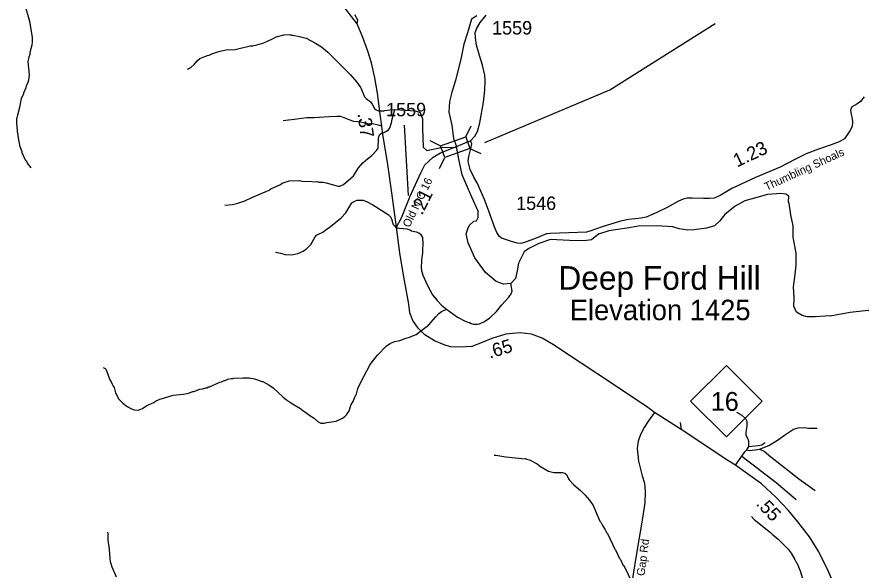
# Model space of a CAD drawing. Extents: x 1248224 to 1454986, y 825081 to 985870.
# Drawn here: x 1328841 to 1336688, y 907441 to 912588 of the extents above; entities that cross this region are included whole.
import ezdxf

# ---------------------------------------------------------------- set-up
doc = ezdxf.new("R2010")
doc.units = 0
for name, color, linetype in [('Exist Geographical Mountain Summit Elevation Number Label', 7, 'Continuous'), ('Exist Geographical Mountain Summit Label', 7, 'Continuous'), ('Exist Hydrographic Misc Water Feature', 7, 'Continuous'), ('Exist Hydrographic River Shore', 7, 'Continuous'), ('Exist Road Non-System Type 51', 7, 'Continuous'), ('Exist Road Primary NC Attributed', 7, 'Continuous'), ('Exist Road Primary NC Mileage Hundredths English Label', 7, 'Continuous'), ('Exist Road Primary NC Shield CELL', 7, 'Continuous'), ('Exist Road Primary NC Shield Number Label', 7, 'Continuous'), ('Exist Road Secondary Mileage Hundredths English Label', 7, 'Continuous'), ('Exist Road Secondary Structure Standard Bridge CELL', 7, 'Continuous'), ('Exist Road Secondary Structure Standard Bridge Number Label', 7, 'Continuous'), ('Exist Road Secondary Type 51 Attributed', 7, 'Continuous'), ('Exist Road Secondary Type 51 Label', 7, 'Continuous'), ('Exist Road Secondary Type 51 Number Label', 7, 'Continuous')]:
    doc.layers.add(name, color=color, linetype=linetype)

msp = doc.modelspace()

# ---------------------------------------------------------------- linework, layer by layer
at = {"layer": 'Exist Hydrographic Misc Water Feature'}
for points in [[(1328974.7, 911185), (1328939.9, 911226), (1328932.4, 911242.2), (1328924.6, 911250.4), (1328890.7, 911323.4), (1328890.9, 911331.4), (1328872.2, 911379.9), (1328858.1, 911444.3), (1328846.3, 911524.7), (1328840.5, 911604.8), (1328841.5, 911636.8), (1328848.5, 911676.5), (1328868.5, 911748), (1328884.8, 911827.5), (1328904.1, 911874.9), (1328904.4, 911882.9), (1328927.7, 911930.2), (1328930.2, 911948.1), (1328945.1, 911979.7), (1328951.8, 912001.4), (1328957.1, 912049.3), (1328946.4, 912169.6), (1328955.8, 912217.3), (1328964.5, 912241), (1328965, 912259), (1328982.9, 912328.5), (1328985.6, 912352.4), (1328985, 912400.4), (1328961, 912545), (1328913.5, 912706.4)], [(1330425.3, 912102.8), (1330457.6, 912115.9), (1330488.4, 912145), (1330515.4, 912178.2), (1330540, 912199.5), (1330572.4, 912214.6), (1330588.6, 912218.1), (1330612.9, 912229.4), (1330629, 912232.9), (1330653.3, 912244.2), (1330718, 912266.4), (1330782.4, 912280.4), (1330870.6, 912286), (1331007.5, 912317.9), (1331031.6, 912319.3), (1331071.9, 912328.1), (1331136.4, 912346.2), (1331217.5, 912383.9), (1331250.1, 912402.9), (1331322.6, 912420.8), (1331376.7, 912423.2), (1331390.6, 912418.8), (1331406.6, 912418.4), (1331414.5, 912414.1), (1331456.3, 912409), (1331529.8, 912390.8), (1331616.5, 912344.3), (1331673.6, 912308.7), (1331732.2, 912259), (1331940.4, 912049), (1332000.5, 911981.3), (1332037.1, 911928.2), (1332072.8, 911845.3), (1332088.3, 911828.8), (1332127.4, 911797.7), (1332142.9, 911777.2), (1332165.8, 911736.6), (1332179.4, 911724.2), (1332203.2, 911715.5), (1332251.2, 911714.2), (1332259.3, 911718), (1332307.5, 911724.5), (1332352.2, 911725.5)], [(1330773.8, 910835.1), (1330846.1, 910843), (1330894.3, 910853.7), (1330958.9, 910875.7), (1331023.9, 910907.9), (1331185.9, 910977.2), (1331202.2, 910988.7), (1331291.4, 911030.1), (1331307.8, 911041.6), (1331372.4, 911063.7), (1331466.5, 911065.1), (1331488.4, 911060.4), (1331582.4, 911057.7), (1331620.2, 911052.6), (1331634.4, 911056.2), (1331648.2, 911051.7), (1331686.3, 911050.7), (1331700.1, 911046.3), (1331716.1, 911045.8), (1331827.2, 911014.6), (1331843.2, 911014.1), (1331875.7, 911029.2), (1331945.3, 911087.2), (1331968, 911110.5), (1332016.1, 911183.1), (1332057.4, 911229.9), (1332098.5, 911266.7), (1332139.4, 911297.5), (1332184.7, 911344.2), (1332197.3, 911367.8), (1332201.9, 911455.7), (1332204.3, 911471.6), (1332212.9, 911493.3), (1332229.3, 911506.9), (1332245.4, 911510.3), (1332269.7, 911521.6), (1332294.2, 911538.9), (1332308.7, 911556.5), (1332324.1, 911604.1), (1332329, 911635.9), (1332352.2, 911725.5)], [(1332352.2, 911725.5), (1332456.7, 911720.5), (1332543, 911714.8), (1332589, 911697.5), (1332612, 911640), (1332612, 911553.7), (1332617.7, 911375.3), (1332652.2, 911346.5), (1332796, 911375.3), (1332929.9, 911373.4)], [(1331245.7, 910399.6), (1331291.4, 910390.2), (1331333.2, 910377.1), (1331397, 910373.2), (1331453.4, 910385.6), (1331502.1, 910408.2), (1331534.8, 910433.2), (1331573.9, 910470.1), (1331611.8, 910541), (1331626.3, 910556.5), (1331642.7, 910568.1), (1331683.2, 910586.9), (1331724.1, 910617.8), (1331756.6, 910636.7), (1331854.9, 910717.9), (1331898.3, 910764.7), (1331955, 910859), (1331971.3, 910870.5), (1332003.7, 910883.5), (1332059.7, 910883.9), (1332095.3, 910868.9), (1332150.5, 910839.3), (1332292.1, 910751.2), (1332315.4, 910724.6), (1332330.4, 910692.2), (1332330.2, 910684.2), (1332339.4, 910657.9), (1332360.9, 910635.3), (1332376.6, 910626.9), (1332396.4, 910622.3), (1332464.3, 910616.3), (1332492.1, 910607.5), (1332507.9, 910599.1), (1332551.7, 910589.8), (1332577.3, 910579), (1332593, 910566.6), (1332610.1, 910536.1), (1332609.5, 910512.2), (1332613.3, 910504.1), (1332610.1, 910392.2), (1332600.3, 910328.4), (1332598.1, 910248.6), (1332601.8, 910240.5), (1332601.4, 910224.5), (1332609, 910208.3), (1332614.2, 910184.1), (1332653.8, 910095), (1332705.3, 910003.5), (1332747.7, 909948.3), (1332788.5, 909905.1), (1332832.7, 909869)], [(1332832.7, 909869), (1332937.5, 909794.9), (1333008.4, 909756.8), (1333040.1, 909743.9), (1333048.1, 909743.7), (1333063.8, 909735.2), (1333083.7, 909730.7), (1333123.7, 909729.5), (1333139.8, 909733.1), (1333188.5, 909755.6), (1333237.4, 909788.2), (1333299.1, 909848.4), (1333348.9, 909910.9), (1333414.9, 909981), (1333423.4, 909996.8), (1333431.6, 910004.5), (1333444.5, 910036.1), (1333430.7, 910106.7)], [(1329642.8, 909326.2), (1329660.5, 909317.7), (1329666.4, 909309.6), (1329687.1, 909265), (1329701.8, 909216.6), (1329717, 909192.1), (1329735.9, 909151.6), (1329745.6, 909139.3), (1329756.2, 909091), (1329788.6, 909032.2), (1329825.5, 908993.1), (1329864.7, 908964), (1329906.1, 908942.8), (1329931.9, 908934.1), (1329967.8, 908931), (1329975.9, 908932.7), (1330008.3, 908945.9), (1330049, 908972.6), (1330113.8, 909000.7), (1330130.2, 909012.3), (1330170.7, 909031.1), (1330203.1, 909042.1), (1330291.8, 909067.6), (1330388.2, 909076.8), (1330436.5, 909087.3), (1330476.9, 909102.2), (1330484.9, 909102), (1330541.5, 909124.4), (1330565.6, 909127.6), (1330597.9, 909138.7), (1330605.9, 909138.5), (1330622.1, 909146), (1330630.1, 909145.8), (1330727.5, 909190.9), (1330743.6, 909194.5), (1330767.9, 909205.8), (1330775.9, 909205.6), (1330800.2, 909216.8), (1330832.4, 909223.9), (1330848.4, 909223.4), (1330856.6, 909227.2), (1330944.7, 909230.7), (1331000.7, 909229), (1331048.5, 909221.7), (1331119.8, 909195.6), (1331127.8, 909195.4), (1331183, 909165.8), (1331222.2, 909136.7), (1331315.8, 909049.9), (1331347.1, 909025.1), (1331394.3, 908995.7), (1331402, 908987.5), (1331476.9, 908945.3), (1331484.7, 908937.1), (1331539.6, 908899.5), (1331563.1, 908878.9), (1331602.4, 908853.8), (1331641.4, 908820.6), (1331665.1, 908808), (1331697.1, 908807), (1331721.3, 908814.3), (1331809.8, 908827.8), (1331866.5, 908854.1), (1331888.9, 908869.5), (1331903.4, 908885.1), (1331928.5, 908924.3), (1331948.1, 908981.7), (1331965, 909011.2), (1331977.9, 909044.8), (1331997, 909082.2), (1332010.3, 909129.9), (1332038, 909189.1), (1332122.5, 909348.6), (1332141.5, 909380), (1332191.2, 909442.5), (1332277.6, 909528), (1332310.2, 909549), (1332350.8, 909567.9), (1332399.1, 909578.4), (1332455.7, 909598.8), (1332479.9, 909604.2), (1332552.8, 909634), (1332667.2, 909720.7), (1332733.5, 909798.8), (1332762.3, 909827.9), (1332786.9, 909847.2), (1332832.7, 909869)], [(1333277.6, 908511.4), (1333293.6, 908510.9), (1333385.1, 908494.3), (1333564.6, 908477.1), (1333570.7, 908479), (1333576.6, 908474.8), (1333604.4, 908468), (1333675.4, 908429.9), (1333706.7, 908405), (1333783.5, 908362.8), (1333833.2, 908349.4), (1333913.3, 908351.1), (1333935.2, 908344.4), (1333948.7, 908330.1), (1333963.8, 908295.6), (1333973.4, 908281.4), (1334018.1, 908236.1), (1334080.6, 908182.2), (1334119.5, 908141.1), (1334162.2, 908091.9), (1334196.7, 908042.9), (1334260.7, 907897.1), (1334268.5, 907888.9), (1334283.5, 907856.5), (1334306.6, 907823.8), (1334321.7, 907791.4), (1334329.5, 907783.2), (1334397.5, 907637.3), (1334405.2, 907629), (1334443, 907548), (1334450.7, 907539.7), (1334473.3, 907491.1), (1334481.1, 907482.9), (1334560.7, 907322.7)], [(1335669.9, 907940.4), (1335693.8, 907913.7), (1335846.5, 907791.3), (1335861.9, 907774.9), (1335916.7, 907729.3), (1336010.1, 907636.6), (1336037, 907597.8), (1336071.5, 907540.8), (1336082.8, 907516.5), (1336090.6, 907508.3), (1336120.5, 907435.4), (1336142.4, 907362.9), (1336187.8, 907265.6), (1336195.6, 907257.4), (1336218.2, 907208.8), (1336237.3, 907175.7), (1336291, 907092.6), (1336388.6, 906972)], [(1329683.7, 907793.6), (1329687.3, 907777.5), (1329685.7, 907721.5), (1329699.3, 907637.1), (1329704.7, 907545), (1329708.1, 907522.9), (1329722.7, 907472.5), (1329764.1, 907379.4)]]:
    msp.add_lwpolyline(points, dxfattribs=at)
at = {"layer": 'Exist Hydrographic River Shore'}
for points in [[(1333115.5, 912598.9), (1333066.8, 912567.6), (1333028.6, 912439), (1332993.9, 912334.7), (1332969.6, 912209.5), (1332917.1, 911995.9), (1332882.4, 911888.2), (1332861.5, 911801.3), (1332854.6, 911700.4), (1332882.4, 911582.2), (1332899.8, 911457.1), (1332928.2, 911382.5)], [(1336401, 909808), (1336260.4, 909798.4), (1336187.5, 909798.4), (1336138.8, 909808.8), (1336086.7, 909840.1), (1336062.4, 909895.7), (1336065.9, 909972.2), (1336058.9, 910076.5), (1336076.3, 910191.2), (1336083.2, 910278.1), (1336083.2, 910389.4), (1336055.5, 910538.9), (1336055.5, 910643.2), (1336034.6, 910747.4), (1336020.7, 910851.7), (1336013.8, 910869.1), (1336017.2, 910921.3), (1335989.4, 910938.6), (1335940.8, 910945.6), (1335819.2, 910935.2), (1335718.5, 910907.4), (1335607.3, 910876.1), (1335517, 910827.4), (1335419.7, 910750.9), (1335374.6, 910691.8), (1335325.9, 910643.2), (1335249.5, 910622.3), (1335134.9, 910608.4), (1335075.8, 910604.9), (1334995.9, 910615.3), (1334936.9, 910636.2), (1334787.5, 910643.2), (1334617.3, 910639.7), (1334509.6, 910622.3), (1334342.9, 910598), (1334245.6, 910566.7), (1334183.1, 910514.5), (1334113.6, 910504.1), (1333978.1, 910507.6), (1333860, 910514.5), (1333800.9, 910518), (1333693.3, 910479.8), (1333599.5, 910434.6), (1333556.3, 910403.4), (1333528.5, 910347.8), (1333504.2, 910295.6), (1333490.3, 910226.1), (1333476.4, 910153.1), (1333430.7, 910106.7), (1333365.3, 910100.9), (1333295.8, 910125.3), (1333195, 910208.7), (1333097.8, 910347.8), (1333035.2, 910486.8), (1333017.9, 910570.2), (1333031.8, 910615.4), (1333049.1, 910650.2), (1333087.4, 910688.4), (1333111.7, 910691.9), (1333129, 910723.2), (1333129, 910782.3), (1333070, 910910.9), (1332979.7, 911119.5), (1332948.6, 911263.9), (1332928.2, 911382.5)], [(1336401, 909808), (1336585.6, 909841.9), (1336754.8, 909860.4), (1336957.9, 909838.8), (1337136.3, 909804.9), (1337259.4, 909749.5)]]:
    msp.add_lwpolyline(points, dxfattribs=at)
at = {"layer": 'Exist Road Non-System Type 51'}
for points in [[(1332234.4, 911571.1), (1332201.2, 911580.8), (1332158.3, 911590.6), (1332103.6, 911594.5), (1332033.4, 911610.1), (1332006.1, 911612.1), (1331972.9, 911616), (1331929.9, 911631.6), (1331851.9, 911660.9), (1331814.8, 911662.9), (1331742.6, 911659), (1331604, 911649.2), (1331535.7, 911649.2), (1331444, 911637.5), (1331317.1, 911621.9)], [(1335642.8, 908592.4), (1335644.2, 908622.9), (1335642.8, 908641), (1335634.4, 908664.6), (1335620.6, 908692.4), (1335619.2, 908718.8), (1335621.9, 908742.4), (1335628.9, 908779.9), (1335627.5, 908823), (1335615, 908848), (1335581.7, 908879.9), (1335533.1, 908909.1)], [(1335007.4, 908814.6), (1335015.7, 908750.7)], [(1335744, 908565.3), (1335830, 908601.4), (1335896.7, 908640.3), (1335918.9, 908655.6), (1335977.1, 908696.6), (1336021.5, 908728.6), (1336060.4, 908752.2), (1336102, 908764.7), (1336158.9, 908768.9), (1336202, 908761.9), (1336279.7, 908761.9)], [(1335626, 908561.1), (1335642.8, 908592.4)], [(1335642.8, 908592.4), (1335671.9, 908593.8), (1335730.2, 908600.7), (1335764.9, 908606.3), (1335778.8, 908616), (1335795.5, 908629.9)], [(1335579, 908502.2), (1335607.9, 908543.1), (1335626, 908561.1)], [(1335626, 908561.1), (1335646.8, 908554.2), (1335675.9, 908557), (1335746.7, 908565.3)], [(1335744, 908565.3), (1335786.9, 908546.6), (1335848, 908496.6), (1336003.5, 908375.7), (1336110.3, 908291), (1336261.4, 908181.8)], [(1335521.7, 908417.6), (1335579, 908502.2)], [(1335579, 908502.2), (1335896.9, 908256.3), (1336084.1, 908097.1)]]:
    msp.add_lwpolyline(points, dxfattribs=at)
at = {"layer": 'Exist Road Primary NC Attributed'}
for points in [[(1332004.4, 912523.4), (1331792.4, 912798.5), (1331642.7, 912931.3), (1331374.7, 913154.3), (1331089.9, 913405.4), (1330760.3, 913694.2), (1330619.6, 913790), (1330506.9, 913853.9), (1330372.2, 913906.8), (1330349.7, 913915), (1330263.6, 913944.4), (1330081.4, 913963.3), (1329953.8, 913956.4), (1329804.5, 913920.6), (1329582.3, 913849.2)], [(1332369.6, 910631.7), (1332325, 910951.3), (1332289.1, 911214), (1332243.2, 911497.5), (1332234.4, 911571.1), (1332217.4, 911684.4), (1332193.4, 911878.1), (1332167.5, 912021.8), (1332137.6, 912161.6), (1332103.6, 912269.4), (1332057.7, 912395.2), (1332004.4, 912523.4)], [(1334766.3, 908907.7), (1334705.1, 908953.6), (1334366.8, 909179.5), (1334085, 909365.7), (1334077.4, 909372.4), (1333830, 909536.1), (1333722.3, 909600), (1333624.5, 909637.9), (1333518.8, 909647.9), (1333447, 909643.9), (1333385.1, 909635.9), (1333254.2, 909596), (1333166.4, 909560.1), (1333068.7, 909522.1), (1332959, 909514.1), (1332871.2, 909518.1), (1332813.3, 909538.1), (1332721.5, 909574), (1332631.8, 909629.9), (1332571.9, 909691.8), (1332522, 909763.7), (1332492.1, 909835.6), (1332484.2, 909916.2), (1332430.4, 910203.7), (1332400.5, 910393.4), (1332369.6, 910631.7)], [(1336661.4, 906814.7), (1336516.4, 907126.5), (1336382, 907436.3), (1336296.2, 907611), (1336209.7, 907750.3), (1336101, 907891.1), (1336012.5, 907996.3), (1335893.8, 908121.1), (1335763.1, 908243.9), (1335589.6, 908367.7), (1335521.7, 908417.6), (1335449.6, 908462.6), (1335015.7, 908750.7), (1334766.3, 908907.7)]]:
    msp.add_lwpolyline(points, dxfattribs=at)
at = {"layer": 'Exist Road Primary NC Shield CELL'}
msp.add_lwpolyline([(1335103.4, 909013), (1335436.4, 909346), (1335769.4, 909013), (1335436.4, 908680)], close=True, dxfattribs=at)
at = {"layer": 'Exist Road Secondary Structure Standard Bridge CELL'}
for p, q in [((1333013.7, 911471.7), (1333062.7, 911573.7)), ((1332677.6, 911439.1), (1332779.6, 911390.1)), ((1333051.1, 911364.9), (1333153.1, 911315.8)), ((1332768.9, 911178.8), (1332817.9, 911280.8))]:
    msp.add_line(p, q, dxfattribs=at)
msp.add_lwpolyline([(1332779.6, 911390.1), (1333013.5, 911472.2), (1333051.8, 911362.9), (1332817.9, 911280.8)], close=True, dxfattribs=at)
at = {"layer": 'Exist Road Secondary Structure Standard Bridge Number Label'}
msp.add_lwpolyline([(1333190.3, 911420), (1334351.9, 911910.1), (1335332, 912527.2)], dxfattribs=at)
at = {"layer": 'Exist Road Secondary Type 51 Attributed'}
for points in [[(1332004.4, 912523.4), (1332009.4, 912558.6), (1331981.7, 912606.4)], [(1333057.4, 911435.3), (1333096.1, 911478.9), (1333122.4, 911521.6), (1333145.4, 911603.9), (1333176.6, 911794.7), (1333191.4, 911905.8), (1333193.1, 911999.5), (1333189.8, 912047.2), (1333170.1, 912139.3), (1333142.1, 912228.1), (1333114.2, 912325.2), (1333102.7, 912392.6), (1333101.2, 912444.3), (1333116, 912483.8), (1333147.2, 912534.8), (1333203.1, 912603.9)], [(1336715.9, 911843), (1336681.3, 911800.6), (1336638.9, 911768.5), (1336600.4, 911750.5), (1336588.9, 911719.7), (1336595.3, 911679.9), (1336605.6, 911642.6), (1336609.4, 911608), (1336604.3, 911566.9), (1336583.7, 911528.4), (1336532.8, 911453.1), (1336485.3, 911424.9), (1336409.6, 911397.9), (1336291.5, 911358.1), (1336178.6, 911315.7), (1336070.8, 911260.5), (1335935.5, 911189.2), (1335705.8, 911094.2), (1335485.1, 910990.2), (1335377.3, 910927.3), (1335321.5, 910903.1), (1335277.9, 910897.9), (1335222.7, 910897.9), (1335118.7, 910900.5), (1335070, 910900.5), (1335034, 910891.5), (1334990.4, 910874.8), (1334878, 910810.9), (1334788.2, 910768.6), (1334689.4, 910726.2), (1334643.2, 910717.2), (1334526.4, 910704.3), (1334450.7, 910687.6), (1334280, 910636.3), (1334176.1, 910596.5), (1334134.6, 910586.3), (1333971.6, 910578.5), (1333797.1, 910573.4), (1333762.5, 910569.6), (1333667.5, 910531), (1333559.7, 910488.6), (1333523.8, 910480.9), (1333490.4, 910482.2), (1333427.5, 910500.2), (1333344.1, 910528.5), (1333323.6, 910549), (1333303.2, 910580.8), (1333282.7, 910624.4), (1333227.5, 910779.8), (1333186.7, 910888.4), (1333118.7, 911043.8), (1333089.2, 911096.4), (1333053.3, 911168.3), (1333035.3, 911244.1), (1333040.4, 911290.3), (1333049.4, 911327.6), (1333062.2, 911375.1), (1333069.9, 911405.9), (1333057.4, 911435.3)], [(1332928.2, 911382.5), (1333008.9, 911417), (1333057.4, 911435.3)], [(1332369.6, 910631.7), (1332414.8, 910719.7), (1332495.2, 910920.8), (1332595.7, 911137.1), (1332633.4, 911212.5), (1332666.1, 911242.7), (1332708.8, 911282.9), (1332778.1, 911323.5), (1332928.2, 911382.5)], [(1334766.3, 908907.7), (1334712.1, 908831.4), (1334670.5, 908769), (1334638.2, 908703.1), (1334616.2, 908641.9), (1334606.9, 908574.4), (1334611.5, 908515.4), (1334619.6, 908455.3), (1334653.1, 908317.8), (1334673.9, 908249.6), (1334682.1, 908173), (1334676.3, 908069), (1334657.8, 907944.2), (1334596.7, 907577.5), (1334541.4, 907230.6)]]:
    msp.add_lwpolyline(points, dxfattribs=at)
at = {"layer": 'Exist Road Secondary Type 51 Number Label'}
msp.add_line((1332479.5, 910925.9), (1332442.8, 911581.3), dxfattribs=at)

# ---------------------------------------------------------------- texts
at = {"layer": 'Exist Geographical Mountain Summit Elevation Number Label'}
msp.add_text('Elevation 1425', height=190, dxfattribs=at).set_placement((1333979.3, 909766.7))
at = {"layer": 'Exist Geographical Mountain Summit Label'}
msp.add_text('Deep Ford Hill', height=220, dxfattribs=at).set_placement((1333874.4, 910049.5))
at = {"layer": 'Exist Road Primary NC Mileage Hundredths English Label'}
for s, rotation, p in [('.37', 277.87485, (1332006.4, 911688)), ('.65', 16.96044, (1333236, 909408.3)), ('.55', 313.56882, (1335704, 908052.4))]:
    msp.add_text(s, height=125, rotation=rotation, dxfattribs=at).set_placement(p)
at = {"layer": 'Exist Road Primary NC Shield Number Label'}
msp.add_text('16', height=175, dxfattribs=at).set_placement((1335290.5, 908923.3))
at = {"layer": 'Exist Road Secondary Mileage Hundredths English Label'}
for s, rotation, p in [('1.23', 25.23452, (1335535.4, 911186.8)), ('.21', 63.45289, (1332606.5, 910737.4))]:
    msp.add_text(s, height=125, rotation=rotation, dxfattribs=at).set_placement(p)
at = {"layer": 'Exist Road Secondary Type 51 Label'}
for s, rotation, p in [('Thumbling Shoals', 24.63949, (1335809.6, 910969.9)), ('Old N C 16', 64.10237, (1332489.5, 910622.5)), ('Shingle Gap Rd', 82.84371, (1334629.2, 907024.3))]:
    msp.add_text(s, height=75, rotation=rotation, dxfattribs=at).set_placement(p)
at = {"layer": 'Exist Road Secondary Type 51 Number Label'}
for s, p in [('1559', (1333257.8, 912424.2)), ('1559', (1332272.5, 911663.5)), ('1546', (1333481.4, 910792))]:
    msp.add_text(s, height=125, dxfattribs=at).set_placement(p)

doc.saveas('drawing.dxf')
